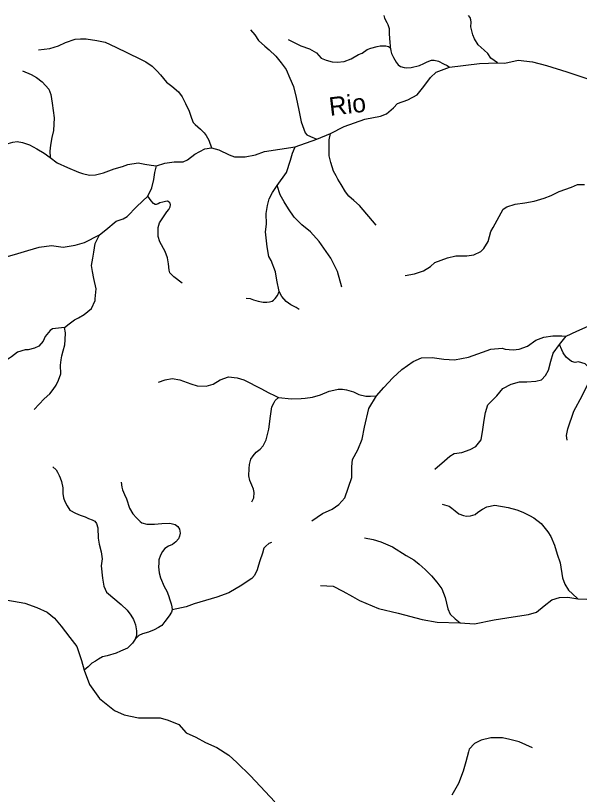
# Model space of a CAD drawing. Extents: x 436.3 to 500.4, y 8231 to 8286.4.
# Drawn here: x 488.75 to 494.87, y 8277.89 to 8286.35 of the extents above; entities that cross this region are included whole.
import ezdxf
from ezdxf.enums import TextEntityAlignment as Align

# ---------------------------------------------------------------- set-up
doc = ezdxf.new("R2010")
doc.units = 0
doc.header["$LTSCALE"] = 0.08
doc.linetypes.add('LONG_DASHED', pattern=[7.5, 6, -1.5])
doc.layers.add('61', color=7, linetype='Continuous')
doc.layers.add('9', color=7, linetype='LONG_DASHED', lineweight=25)

msp = doc.modelspace()

# ---------------------------------------------------------------- linework, layer by layer
at = {"layer": '9'}
for points in [[(492.8195, 8285.9903), (492.8208, 8286.0203), (492.8168, 8286.0568), (492.8091, 8286.1518), (492.8072, 8286.2044), (492.7951, 8286.2489), (492.783, 8286.2712), (492.7663, 8286.302), (492.7575, 8286.3229), (492.7509, 8286.349)], [(493.9828, 8285.8341), (493.9113, 8285.8851), (493.8771, 8285.9362), (493.837, 8285.973), (493.7741, 8286.0297), (493.7342, 8286.0978), (493.7142, 8286.1402), (493.7029, 8286.1828), (493.6944, 8286.2253), (493.6946, 8286.2792), (493.693, 8286.3046), (493.6844, 8286.3295), (493.6674, 8286.3493)], [(491.2993, 8286.1931), (491.3439, 8286.1386), (491.3868, 8286.08), (491.4532, 8286.0176), (491.5, 8285.9786), (491.5742, 8285.9083), (491.6327, 8285.8341), (491.6873, 8285.7639), (491.7261, 8285.6702), (491.7648, 8285.5804), (491.7956, 8285.4595), (491.8224, 8285.3228), (491.8493, 8285.194), (491.8763, 8285.1158), (491.8918, 8285.0767), (491.9113, 8285.0533), (491.9504, 8285.0338), (492.0188, 8285.0056)], [(488.9941, 8285.9786), (489.1182, 8285.9923), (489.2102, 8286.0198), (489.2884, 8286.0564), (489.3941, 8286.0929), (489.4493, 8286.0975), (489.5135, 8286.0975), (489.6283, 8286.0793), (489.7201, 8286.0611), (489.8348, 8286.0063), (490.0959, 8285.8784), (490.1599, 8285.8463), (490.2286, 8285.8006), (490.2834, 8285.7458), (490.3199, 8285.7046), (490.3838, 8285.6269), (490.4432, 8285.5812), (490.5163, 8285.5213), (490.5573, 8285.4664), (490.5936, 8285.3933), (490.63, 8285.311), (490.6572, 8285.2332), (490.6752, 8285.1875), (490.6981, 8285.1646), (490.7255, 8285.1417), (490.7563, 8285.1161), (490.7934, 8285.0758), (490.8167, 8285.0456), (490.8439, 8284.9953), (490.8728, 8284.9117)], [(491.7069, 8286.0884), (491.8438, 8286.0223), (491.941, 8285.987), (492.0162, 8285.9429), (492.0646, 8285.8857), (492.1222, 8285.8635), (492.1841, 8285.846), (492.2417, 8285.8415), (492.317, 8285.8503), (492.3926, 8285.881), (492.4725, 8285.925), (492.5125, 8285.9426), (492.5659, 8285.9822), (492.6052, 8285.9967), (492.674, 8286.0125), (492.7092, 8286.0205), (492.7349, 8286.0204), (492.77, 8286.0188), (492.7988, 8286.0125), (492.8099, 8286.0046), (492.8195, 8285.9903)], [(492.8195, 8285.9903), (492.8226, 8285.9649), (492.8289, 8285.9364), (492.8512, 8285.8951), (492.8813, 8285.8427), (492.9042, 8285.8154), (492.9297, 8285.7964), (492.9665, 8285.7837), (492.9985, 8285.7805), (493.0433, 8285.7853), (493.1331, 8285.8075), (493.1828, 8285.8297), (493.2181, 8285.8471), (493.2662, 8285.863), (493.2949, 8285.8662), (493.343, 8285.8535), (493.3941, 8285.8266), (493.4341, 8285.8075), (493.4597, 8285.7885)], [(492.1688, 8285.0674), (492.3152, 8285.1429), (492.5423, 8285.2234), (492.7099, 8285.2556), (492.7749, 8285.2825), (492.8508, 8285.3468), (492.8942, 8285.3951), (493.0079, 8285.4327), (493.1108, 8285.4864), (493.1815, 8285.5774), (493.2542, 8285.6758), (493.3172, 8285.7328), (493.4597, 8285.7885)], [(493.4597, 8285.7885), (493.7878, 8285.8283), (493.9828, 8285.8341)], [(493.9828, 8285.8341), (494.063, 8285.8314), (494.207, 8285.864), (494.3637, 8285.8482), (494.5149, 8285.8056), (494.7363, 8285.7365), (494.9867, 8285.6557)], [(488.8204, 8285.7492), (488.913, 8285.7078), (488.973, 8285.6779), (489.033, 8285.6309), (489.1057, 8285.5499), (489.1271, 8285.4901), (489.144, 8285.3961), (489.165, 8285.2379), (489.1562, 8285.1012), (489.1388, 8285.0242), (489.1258, 8284.9429), (489.117, 8284.8745), (489.1212, 8284.806)], [(488.1593, 8285.1957), (488.1936, 8285.1832), (488.2495, 8285.1494), (488.3149, 8285.101), (488.3489, 8285.06), (488.3756, 8285.0139), (488.4095, 8284.9486), (488.4264, 8284.9268), (488.4458, 8284.9099), (488.4847, 8284.9003), (488.5333, 8284.9051), (488.5892, 8284.9148), (488.6645, 8284.9585), (488.7146, 8284.9749), (488.7631, 8284.9797), (488.8214, 8284.97), (488.8966, 8284.9435), (488.9766, 8284.9024), (489.0541, 8284.854), (489.1212, 8284.806)], [(490.8728, 8284.9117), (490.9535, 8284.8902), (491.0663, 8284.8364), (491.1254, 8284.8149), (491.2385, 8284.8149), (491.3516, 8284.8364), (491.4487, 8284.874), (491.7854, 8284.9226), (492.0188, 8285.0056), (492.1688, 8285.0674)], [(492.6632, 8284.0728), (492.4825, 8284.2873), (492.4221, 8284.3405), (492.3679, 8284.3887), (492.3297, 8284.4327), (492.2838, 8284.5142), (492.2483, 8284.571), (492.2307, 8284.6065), (492.1989, 8284.6596), (492.1708, 8284.7519), (492.1533, 8284.8264), (492.1538, 8284.9327), (492.1541, 8285.0001), (492.1688, 8285.0674)], [(490.2751, 8284.7182), (490.3664, 8284.7449), (490.4687, 8284.761), (490.5656, 8284.761), (490.6141, 8284.7826), (490.695, 8284.8418), (490.8028, 8284.901), (490.8728, 8284.9117)], [(491.5893, 8284.5019), (491.6894, 8284.6438), (491.7323, 8284.7798), (491.7539, 8284.8544), (491.7854, 8284.9226)], [(489.1212, 8284.806), (489.197, 8284.75), (489.3085, 8284.6992), (489.4272, 8284.6484), (489.4733, 8284.6339), (489.5472, 8284.6163), (489.6126, 8284.6187), (489.7024, 8284.6406), (489.8164, 8284.6842), (489.9084, 8284.7108), (489.9667, 8284.7326), (490.0757, 8284.7496), (490.1484, 8284.7352), (490.217, 8284.723), (490.2751, 8284.7182)], [(490.1833, 8284.3863), (490.2272, 8284.476), (490.2463, 8284.5699), (490.2591, 8284.645), (490.2751, 8284.7182)], [(492.9777, 8283.5267), (493.0806, 8283.543), (493.1779, 8283.5754), (493.2538, 8283.624), (493.3026, 8283.6672), (493.4379, 8283.7158), (493.5299, 8283.7376), (493.649, 8283.7378), (493.7247, 8283.7486), (493.8006, 8283.7865), (493.8331, 8283.8189), (493.882, 8283.8944), (493.9093, 8284.0022), (493.9364, 8284.0453), (494.0451, 8284.2446), (494.083, 8284.2716), (494.1751, 8284.2987), (494.2779, 8284.315), (494.3808, 8284.3315), (494.489, 8284.3641), (494.5665, 8284.3931), (494.6531, 8284.4364), (494.7884, 8284.4853), (494.8534, 8284.5123), (494.9291, 8284.5126)], [(491.6082, 8283.3528), (491.5833, 8283.4736), (491.5691, 8283.566), (491.5229, 8283.6868), (491.4981, 8283.733), (491.4805, 8283.8361), (491.463, 8283.9995), (491.4703, 8284.0813), (491.467, 8284.1976), (491.4815, 8284.2865), (491.4995, 8284.3574), (491.5388, 8284.4285), (491.5893, 8284.5019)], [(492.2923, 8283.3989), (492.244, 8283.5674), (492.1718, 8283.7118), (492.096, 8283.8203), (492.0427, 8283.8949), (491.9503, 8283.9978), (491.8545, 8284.0759), (491.7729, 8284.1576), (491.7128, 8284.2499), (491.6633, 8284.3244), (491.6209, 8284.4025), (491.5893, 8284.5019)], [(489.6567, 8283.9675), (489.7257, 8284.0228), (489.8385, 8284.1168), (489.9137, 8284.1419), (489.9575, 8284.167), (490.0641, 8284.2735), (490.1833, 8284.3863)], [(490.5572, 8283.44), (490.4635, 8283.5088), (490.4198, 8283.5527), (490.4135, 8283.584), (490.4074, 8283.653), (490.3949, 8283.7156), (490.3699, 8283.7845), (490.3138, 8283.8909), (490.2952, 8283.9473), (490.2952, 8283.9973), (490.2953, 8284.0474), (490.308, 8284.0975), (490.3895, 8284.2166), (490.4118, 8284.2414), (490.4263, 8284.2718), (490.4279, 8284.2936), (490.4251, 8284.311), (490.4135, 8284.3211), (490.3961, 8284.3313), (490.3744, 8284.3298), (490.3454, 8284.3225), (490.3135, 8284.3152), (490.2932, 8284.3036), (490.2715, 8284.2978), (490.2628, 8284.2978), (490.2439, 8284.3065), (490.2194, 8284.3355), (490.1833, 8284.3863)], [(487.2179, 8283.2757), (487.2932, 8283.2883), (487.4126, 8283.282), (487.5408, 8283.2686), (487.6538, 8283.2624), (487.7353, 8283.2874), (487.8546, 8283.3188), (488.0553, 8283.4066), (488.1683, 8283.4881), (488.2372, 8283.5007), (488.3439, 8283.5195), (488.4129, 8283.5572), (488.4756, 8283.6136), (488.5572, 8283.6826), (488.6575, 8283.7328), (488.7703, 8283.7642), (488.8769, 8283.7956), (489.0023, 8283.8333), (489.1338, 8283.8521), (489.2622, 8283.8346), (489.3936, 8283.8534), (489.4939, 8283.8849), (489.6567, 8283.9675)], [(489.2751, 8282.9585), (489.3288, 8283.001), (489.3853, 8283.0435), (489.4299, 8283.0658), (489.4897, 8283.1001), (489.5717, 8283.1653), (489.6084, 8283.253), (489.6112, 8283.2728), (489.6197, 8283.3803), (489.5943, 8283.4935), (489.5801, 8283.5688), (489.5717, 8283.6338), (489.583, 8283.7131), (489.5972, 8283.7781), (489.6115, 8283.8714), (489.6567, 8283.9675)], [(491.2521, 8283.2791), (491.2962, 8283.274), (491.3319, 8283.2604), (491.3812, 8283.2469), (491.4372, 8283.2367), (491.4763, 8283.2367), (491.5052, 8283.2401), (491.5323, 8283.2469), (491.5493, 8283.2572), (491.568, 8283.2742), (491.5918, 8283.3082), (491.6082, 8283.3528)], [(491.8288, 8283.1573), (491.7932, 8283.1786), (491.7363, 8283.207), (491.6865, 8283.2425), (491.6402, 8283.2958), (491.6082, 8283.3528)], [(494.7304, 8282.867), (494.845, 8282.921), (495.0669, 8283.0196), (495.1929, 8283.0584), (495.3501, 8283.1576), (495.5079, 8283.2953)], [(489.2751, 8282.9585), (489.2101, 8282.9529), (489.1451, 8282.9443), (489.1208, 8282.9287), (489.0672, 8282.8636), (489.0446, 8282.8126), (488.9994, 8282.7588), (488.9514, 8282.7361), (488.8807, 8282.7191), (488.8496, 8282.7191), (488.7677, 8282.6907), (488.6998, 8282.6426), (488.6801, 8282.6284), (488.6178, 8282.5859), (488.5755, 8282.5718), (488.5246, 8282.5604), (488.4566, 8282.5463), (488.3804, 8282.5236), (488.3209, 8282.5009), (488.2502, 8282.4754), (488.188, 8282.4499), (488.1427, 8282.4442), (488.1007, 8282.4516), (488.0379, 8282.4766)], [(488.9474, 8282.0674), (489.0574, 8282.1864), (489.1168, 8282.2402), (489.1534, 8282.2855), (489.1845, 8282.3337), (489.2126, 8282.3875), (489.2352, 8282.4582), (489.2351, 8282.5516), (489.2407, 8282.607), (489.2491, 8282.6522), (489.2632, 8282.706), (489.2802, 8282.7711), (489.2857, 8282.8249), (489.2886, 8282.9013), (489.2751, 8282.9585)], [(492.6666, 8282.2174), (492.7456, 8282.3097), (492.8434, 8282.414), (492.9413, 8282.5053), (493.0653, 8282.5901), (493.1567, 8282.6293), (493.2743, 8282.6359), (493.3985, 8282.6164), (493.516, 8282.61), (493.6688, 8282.6391), (493.8191, 8282.6913), (493.9106, 8282.7241), (494.0348, 8282.7373), (494.0674, 8282.7243), (494.1524, 8282.7179), (494.2178, 8282.7245), (494.3092, 8282.7572), (494.4007, 8282.8227), (494.4856, 8282.8555), (494.5836, 8282.8687), (494.6816, 8282.8689), (494.7304, 8282.867)], [(493.3022, 8281.4199), (493.4066, 8281.5111), (493.4653, 8281.5633), (493.511, 8281.5893), (493.5958, 8281.6024), (493.6872, 8281.6349), (493.746, 8281.6675), (493.8047, 8281.7392), (493.8243, 8281.8502), (493.8373, 8281.9547), (493.8511, 8282.0361), (493.8771, 8282.121), (493.9752, 8282.2189), (494.0404, 8282.2973), (494.1318, 8282.3431), (494.2233, 8282.3693), (494.3016, 8282.3693), (494.3997, 8282.376), (494.4594, 8282.3913), (494.5051, 8282.4371), (494.5378, 8282.4959), (494.5639, 8282.5939), (494.587, 8282.6816), (494.6554, 8282.777), (494.7304, 8282.867)], [(494.7399, 8281.7353), (494.7333, 8281.7876), (494.7465, 8281.8596), (494.8117, 8282.0492), (494.9031, 8282.2193), (494.9685, 8282.3502), (494.9881, 8282.4418), (494.9816, 8282.5137), (494.936, 8282.5658), (494.8643, 8282.5853), (494.8251, 8282.5787), (494.7859, 8282.5918), (494.7272, 8282.6373), (494.6945, 8282.683), (494.6815, 8282.7156), (494.6554, 8282.777)], [(490.2973, 8282.3673), (490.3707, 8282.392), (490.4483, 8282.4043), (490.53, 8282.3922), (490.6484, 8282.3472), (490.7179, 8282.3269), (490.8159, 8282.3228), (490.8935, 8282.3433), (490.967, 8282.3925), (491.0609, 8282.4253), (491.1548, 8282.4131), (491.2243, 8282.3927), (491.4165, 8282.2946), (491.4902, 8282.2537), (491.5679, 8282.2169), (491.6031, 8282.2008)], [(491.6031, 8282.2008), (491.7439, 8282.1842), (491.8476, 8282.1886), (491.8926, 8282.1926), (491.9704, 8282.2049), (492.0604, 8282.2296), (492.1545, 8282.2665), (492.2036, 8282.2787), (492.2527, 8282.291), (492.2977, 8282.291), (492.3428, 8282.2828), (492.4166, 8282.2624), (492.474, 8282.2338), (492.5518, 8282.2133), (492.601, 8282.2133), (492.6666, 8282.2174)], [(491.314, 8281.0659), (491.333, 8281.1094), (491.3366, 8281.1664), (491.3294, 8281.2022), (491.3115, 8281.2486), (491.29, 8281.2986), (491.2793, 8281.3485), (491.2824, 8281.4277), (491.2872, 8281.4698), (491.3004, 8281.5305), (491.3254, 8281.5662), (491.361, 8281.6055), (491.4038, 8281.6376), (491.4358, 8281.6734), (491.4679, 8281.7412), (491.4963, 8281.8554), (491.5142, 8281.9973), (491.5318, 8282.0973), (491.5567, 8282.1436), (491.5675, 8282.1686), (491.6031, 8282.2008)], [(491.9649, 8280.861), (492.082, 8280.9391), (492.1863, 8280.9845), (492.258, 8281.0366), (492.323, 8281.1082), (492.4011, 8281.3296), (492.4009, 8281.4468), (492.4074, 8281.525), (492.466, 8281.6292), (492.5115, 8281.7465), (492.5374, 8281.8768), (492.5827, 8282.0789), (492.6666, 8282.2174)], [(489.1493, 8281.4469), (489.188, 8281.4118), (489.202, 8281.3872), (489.2196, 8281.3522), (489.2301, 8281.3276), (489.2441, 8281.2855), (489.2583, 8281.2189), (489.2584, 8281.1556), (489.2654, 8281.11), (489.2795, 8281.0679), (489.3042, 8281.0224), (489.3357, 8280.9768), (489.3954, 8280.9419), (489.4479, 8280.9209), (489.5005, 8280.9034), (489.539, 8280.8859), (489.5777, 8280.8685), (489.6057, 8280.8545), (489.6232, 8280.8299), (489.6408, 8280.7844), (489.6409, 8280.6722), (489.6549, 8280.6056), (489.6759, 8280.5228), (489.6865, 8280.4457), (489.676, 8280.372), (489.6901, 8280.2354), (489.7041, 8280.1479), (489.7321, 8280.0849), (489.8933, 8279.9486), (489.9566, 8279.8879), (489.9986, 8279.8354), (490.0266, 8279.7864), (490.0476, 8279.7305), (490.058, 8279.6641), (490.058, 8279.6151), (490.044, 8279.5731)], [(489.8944, 8281.2789), (489.9, 8281.2268), (489.9082, 8281.1967), (489.9274, 8281.1473), (489.9494, 8281.0981), (489.9823, 8280.9967), (490.0207, 8280.9365), (490.0591, 8280.8926), (490.0975, 8280.8538), (490.1167, 8280.8374), (490.1715, 8280.8238), (490.2564, 8280.8239), (490.3358, 8280.8322), (490.4125, 8280.8323), (490.4344, 8280.8296), (490.481, 8280.8186), (490.5084, 8280.7995), (490.5276, 8280.7694), (490.5331, 8280.7255), (490.5276, 8280.6927), (490.514, 8280.6626), (490.4865, 8280.6297), (490.451, 8280.6023), (490.4072, 8280.583), (490.3661, 8280.5583), (490.3415, 8280.5254), (490.3195, 8280.4853), (490.3031, 8280.4359), (490.3004, 8280.3977), (490.2976, 8280.3593), (490.3058, 8280.2936), (490.3196, 8280.2389), (490.3606, 8280.1459), (490.3881, 8280.0967), (490.4072, 8280.0474), (490.4209, 8280.0009), (490.4345, 8279.9572), (490.4427, 8279.9244), (490.4455, 8279.8916)], [(493.3821, 8281.0412), (493.4577, 8281.0195), (493.4876, 8280.9964), (493.5241, 8280.9698), (493.5639, 8280.9366), (493.6137, 8280.9167), (493.6468, 8280.9099), (493.69, 8280.9132), (493.7398, 8280.9297), (493.7696, 8280.9529), (493.8194, 8280.9859), (493.8658, 8281.0123), (493.9553, 8281.0287), (494.0981, 8281.0054), (494.1909, 8280.9787), (494.2572, 8280.9521), (494.3302, 8280.9188), (494.3767, 8280.8921), (494.4563, 8280.829), (494.5306, 8280.7412), (494.5605, 8280.688), (494.6035, 8280.5951), (494.63, 8280.4956), (494.663, 8280.4027), (494.6894, 8280.2403), (494.7159, 8280.1708), (494.7557, 8280.1044), (494.7987, 8280.0646), (494.8549, 8280.0113)], [(491.5249, 8280.6243), (491.499, 8280.6113), (491.4643, 8280.5855), (491.4426, 8280.5638), (491.4297, 8280.5075), (491.3994, 8280.4253), (491.3863, 8280.3778), (491.3691, 8280.3258), (491.3428, 8280.2641), (491.3124, 8280.2338), (491.2735, 8280.2079), (491.2042, 8280.1603), (491.0612, 8280.0781), (490.9314, 8280.0304), (490.6846, 8279.9568), (490.598, 8279.9265), (490.4455, 8279.8916)], [(492.537, 8280.6757), (492.6306, 8280.6559), (492.7142, 8280.6312), (492.8424, 8280.577), (492.9901, 8280.4834), (493.0738, 8280.4342), (493.1329, 8280.3898), (493.1969, 8280.3307), (493.2659, 8280.2618), (493.325, 8280.1928), (493.3791, 8280.119), (493.4135, 8280.0257), (493.4429, 8279.9028), (493.4675, 8279.8438), (493.5217, 8279.7946), (493.5768, 8279.7501)], [(492.0606, 8280.1566), (492.1984, 8280.1479), (492.3018, 8280.0962), (492.4051, 8280.036), (492.4826, 8279.9929), (492.6893, 8279.9067), (492.9047, 8279.8547), (493.1631, 8279.7855), (493.3269, 8279.7593), (493.5768, 8279.7501)], [(493.5768, 8279.7501), (493.732, 8279.741), (493.9476, 8279.7834), (494.1546, 8279.8171), (494.3184, 8279.8424), (494.4046, 8279.868), (494.4909, 8279.9365), (494.5732, 8280.0023), (494.6561, 8280.0252), (494.7456, 8280.0316), (494.8549, 8280.0113)], [(494.8549, 8280.0113), (494.9544, 8280.0078), (495.0793, 8279.9948), (495.1912, 8279.9945), (495.3119, 8280.0287)], [(488.5779, 8280.013), (488.8468, 8279.9662), (488.9766, 8279.9178), (489.087, 8279.866), (489.1699, 8279.8014), (489.2419, 8279.7151), (489.3361, 8279.5929), (489.4095, 8279.4951), (489.463, 8279.3435), (489.4906, 8279.2372)], [(490.4455, 8279.8916), (490.44, 8279.8669), (490.4151, 8279.8268), (490.3675, 8279.7662), (490.3328, 8279.7229), (490.2982, 8279.7013), (490.2506, 8279.6753), (490.19, 8279.6493), (490.1251, 8279.632), (490.0861, 8279.6146), (490.044, 8279.5731)], [(490.044, 8279.5731), (490.0159, 8279.5311), (489.9598, 8279.4749), (489.8861, 8279.4434), (489.8371, 8279.4223), (489.7388, 8279.3942), (489.6898, 8279.3801), (489.6477, 8279.3556), (489.6126, 8279.3345), (489.5752, 8279.3136), (489.5354, 8279.2714), (489.4906, 8279.2372)], [(489.4906, 8279.2372), (489.5468, 8279.0813), (489.6584, 8278.93), (489.821, 8278.7989), (489.9265, 8278.7505), (490.0806, 8278.7184), (490.316, 8278.7187), (490.4052, 8278.6945), (490.5187, 8278.6461), (490.5997, 8278.5572), (490.7052, 8278.5088), (490.8106, 8278.4522), (490.9322, 8278.3957), (491.0619, 8278.3149), (491.1511, 8278.2339), (491.2969, 8278.0885), (491.4589, 8277.9186), (491.5642, 8277.8054)], [(494.3624, 8278.3932), (494.2171, 8278.457), (494.1172, 8278.4844), (494.0354, 8278.5027), (493.9118, 8278.5009), (493.8061, 8278.4774), (493.734, 8278.4393), (493.6763, 8278.3776), (493.6666, 8278.3489), (493.6375, 8278.2392), (493.6085, 8278.1391), (493.5601, 8278.0057), (493.4878, 8277.877)]]:
    msp.add_lwpolyline(points, dxfattribs=at)

# ---------------------------------------------------------------- texts
at = {"layer": '61'}
msp.add_text('Rio                                     Grande', height=0.2, rotation=6.748, dxfattribs=at).set_placement((494.1705, 8285.4971), align=Align.CENTER)

doc.saveas('drawing.dxf')
